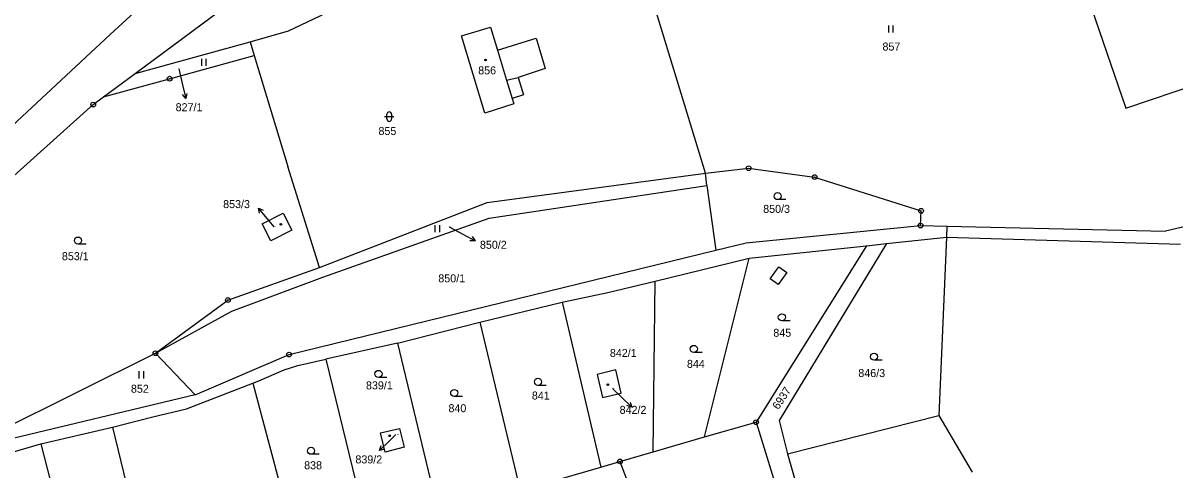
# Model space of a CAD drawing. Extents: x -593183 to -588034, y -1130415 to -1124994.
# Drawn here: x -592013.9 to -591769.2, y -1129007.5 to -1128912.6 of the extents above; entities that cross this region are included whole.
import ezdxf

# ---------------------------------------------------------------- set-up
doc = ezdxf.new("R2010")
doc.units = 0
for name, color, linetype in [('Vrstva 1', 7, 'Continuous'), ('Vrstva 16', 7, 'Continuous'), ('Vrstva 18', 7, 'Continuous'), ('Vrstva 19', 7, 'Continuous'), ('Vrstva 24', 7, 'Continuous'), ('Vrstva 25', 7, 'Continuous'), ('Vrstva 4', 7, 'Continuous')]:
    doc.layers.add(name, color=color, linetype=linetype)

msp = doc.modelspace()

# ---------------------------------------------------------------- linework, layer by layer
at = {"layer": 'Vrstva 1'}
for p, q in [((-591798.16, -1128876.43), (-591779.63, -1128930.63)), ((-591868.9, -1128944.44), (-591882.81, -1128898.89)), ((-591957.53, -1128914.23), (-591926.72, -1128899.6)), ((-591990.07, -1128923.29), (-591972.01, -1128909.95)), ((-591920.76, -1128915.28), (-591914.6, -1128913.44)), ((-591914.6, -1128913.44), (-591913.11, -1128918.34)), ((-591965.66, -1128916.58), (-591957.53, -1128914.23)), ((-591915.78, -1128931.72), (-591920.76, -1128915.28)), ((-591913.11, -1128918.34), (-591904.88, -1128915.79)), ((-591904.88, -1128915.79), (-591902.94, -1128922.26)), ((-591990.07, -1128923.29), (-591965.66, -1128916.58)), ((-591965.66, -1128916.58), (-591964.79, -1128919.47)), ((-591982.75, -1128924.4), (-591964.79, -1128919.47)), ((-591964.79, -1128919.47), (-591957.62, -1128943.06)), ((-591779.63, -1128930.63), (-591749.15, -1128920.45)), ((-591996.78, -1128928.26), (-591990.07, -1128923.29)), ((-591902.94, -1128922.26), (-591908.71, -1128924.16)), ((-591996.78, -1128928.26), (-591982.75, -1128924.4)), ((-591908.71, -1128924.16), (-591907.55, -1128927.85)), ((-591998.99, -1128929.89), (-591996.78, -1128928.26)), ((-591907.55, -1128927.85), (-591909.99, -1128928.59)), ((-592021.3, -1128949.87), (-591998.99, -1128929.89)), ((-591909.65, -1128929.71), (-591915.78, -1128931.72)), ((-591909.99, -1128928.59), (-591909.65, -1128929.71)), ((-591950.91, -1128964.5), (-591957.62, -1128943.06)), ((-591912.67, -1128950.37), (-591868.9, -1128944.44)), ((-591868.9, -1128944.44), (-591859.74, -1128943.42)), ((-591868.6, -1128947.12), (-591868.9, -1128944.44)), ((-591859.74, -1128943.42), (-591845.72, -1128945.3)), ((-591845.72, -1128945.3), (-591823.08, -1128952.47)), ((-591914.85, -1128954), (-591868.6, -1128947.12)), ((-591868.6, -1128947.12), (-591866.69, -1128960.82)), ((-591915.3, -1128950.73), (-591912.67, -1128950.37)), ((-591950.91, -1128964.5), (-591915.3, -1128950.73)), ((-591823.22, -1128955.59), (-591823.08, -1128952.47)), ((-591963.1, -1128955.2), (-591958.61, -1128952.97)), ((-591961.27, -1128958.84), (-591963.1, -1128955.2)), ((-591958.61, -1128952.97), (-591956.79, -1128956.59)), ((-591950.17, -1128966.57), (-591914.85, -1128954)), ((-591764.54, -1128955.26), (-591771.18, -1128956.77)), ((-591956.79, -1128956.59), (-591961.27, -1128958.84)), ((-591860.27, -1128959.25), (-591823.22, -1128955.59)), ((-591823.22, -1128955.59), (-591817.63, -1128955.72)), ((-591817.63, -1128955.72), (-591817.73, -1128958.08)), ((-591817.63, -1128955.72), (-591771.18, -1128956.77)), ((-591866.69, -1128960.82), (-591860.27, -1128959.25)), ((-591859.65, -1128962.55), (-591834.68, -1128959.89)), ((-591834.68, -1128959.89), (-591858.16, -1128997.37)), ((-591830.47, -1128959.44), (-591853.26, -1128997.03)), ((-591834.68, -1128959.89), (-591830.47, -1128959.44)), ((-591830.47, -1128959.44), (-591817.73, -1128958.08)), ((-591817.73, -1128958.08), (-591819.31, -1128995.97)), ((-591817.73, -1128958.08), (-591768.01, -1128959.56)), ((-591957.38, -1128982.99), (-591866.69, -1128960.82)), ((-591879.62, -1128967.39), (-591859.65, -1128962.55)), ((-591869.09, -1129000.5), (-591859.65, -1128962.55)), ((-591970.38, -1128971.43), (-591950.91, -1128964.5)), ((-591969.54, -1128973.78), (-591950.17, -1128966.57)), ((-591889.63, -1128969.81), (-591879.62, -1128967.39)), ((-591880.05, -1129003.67), (-591879.62, -1128967.39)), ((-591899.38, -1128971.86), (-591889.63, -1128969.81)), ((-591985.78, -1128982.71), (-591970.38, -1128971.43)), ((-591916.85, -1128976.13), (-591899.38, -1128971.86)), ((-591899.38, -1128971.86), (-591891.13, -1129006.89)), ((-591985.78, -1128982.71), (-591969.54, -1128973.78)), ((-591934.35, -1128980.55), (-591916.85, -1128976.13)), ((-591916.85, -1128976.13), (-591908.28, -1129011.87)), ((-591934.35, -1128980.55), (-591949.56, -1128983.97)), ((-591934.35, -1128980.55), (-591925.61, -1129016.89)), ((-592027.75, -1129003.63), (-591985.78, -1128982.71)), ((-591985.78, -1128982.71), (-591977.29, -1128991.55)), ((-591977.29, -1128991.55), (-591957.38, -1128982.99)), ((-591949.56, -1128983.97), (-591940.48, -1129021.2)), ((-591887.96, -1128986.26), (-591891.89, -1128987.2)), ((-591886.81, -1128991.2), (-591887.96, -1128986.26)), ((-591979.14, -1128994.54), (-591965.09, -1128989.08)), ((-591965.09, -1128989.08), (-591963.81, -1128988.59)), ((-591965.09, -1128989.08), (-591955.4, -1129025.36)), ((-591891.89, -1128987.2), (-591890.75, -1128992.11)), ((-591977.29, -1128991.55), (-592027.75, -1129003.63)), ((-591890.75, -1128992.11), (-591886.81, -1128991.2)), ((-591994.88, -1128998.43), (-591986.29, -1128996.22)), ((-591986.29, -1128996.22), (-591979.14, -1128994.54)), ((-591851.46, -1129004.08), (-591819.31, -1128995.97)), ((-591819.31, -1128995.97), (-591812.24, -1129007.95)), ((-592010.12, -1129001.94), (-591994.88, -1128998.43)), ((-591994.88, -1128998.43), (-591986.87, -1129031.29)), ((-591869.09, -1129000.5), (-591858.16, -1128997.37)), ((-591858.16, -1128997.37), (-591850.21, -1129022.94)), ((-591853.26, -1128997.03), (-591851.46, -1129004.08)), ((-591880.05, -1129003.67), (-591869.09, -1129000.5)), ((-592024.59, -1129006.21), (-592010.12, -1129001.94)), ((-592010.12, -1129001.94), (-592000.9, -1129037.72)), ((-591887.08, -1129005.69), (-591880.05, -1129003.67)), ((-591851.46, -1129004.08), (-591844.7, -1129027.89)), ((-591891.13, -1129006.89), (-591887.08, -1129005.69)), ((-591887.08, -1129005.69), (-591877.29, -1129031.67)), ((-591908.28, -1129011.87), (-591891.13, -1129006.89))]:
    msp.add_line(p, q, dxfattribs=at)
for points in [[(-591963.81, -1128988.59), (-591958.42, -1128986.25), (-591955.53, -1128985.34), (-591949.56, -1128983.97)], [(-591937.96, -1128999.66), (-591933.94, -1128998.68), (-591932.92, -1129002.7), (-591936.96, -1129003.7), (-591937.96, -1128999.66)]]:
    msp.add_lwpolyline(points, dxfattribs=at)
at = {"layer": 'Vrstva 16'}
for p, q in [((-591980.81, -1128922.31), (-591980.01, -1128925.7)), ((-591960.54, -1128955.89), (-591961.96, -1128954.19)), ((-591923.38, -1128955.89), (-591920.47, -1128957.43)), ((-591888.65, -1128990.2), (-591886.69, -1128992.1)), ((-591934.78, -1129000.05), (-591936.05, -1129001.3))]:
    msp.add_line(p, q, dxfattribs=at)
at = {"layer": 'Vrstva 24'}
for centre, radius in [((-591982.75, -1128924.4), 0.5), ((-591982.75, -1128924.4), 0.0327), ((-591998.99, -1128929.89), 0.5), ((-591998.99, -1128929.89), 0.0327), ((-591859.74, -1128943.42), 0.5), ((-591859.74, -1128943.42), 0.0327), ((-591845.72, -1128945.3), 0.5), ((-591845.72, -1128945.3), 0.0327), ((-591823.08, -1128952.47), 0.5), ((-591823.08, -1128952.47), 0.0327), ((-591823.22, -1128955.59), 0.5), ((-591823.22, -1128955.59), 0.0327), ((-591970.38, -1128971.43), 0.5), ((-591970.38, -1128971.43), 0.0327), ((-591985.78, -1128982.71), 0.5), ((-591985.78, -1128982.71), 0.0327), ((-591957.38, -1128982.99), 0.5), ((-591957.38, -1128982.99), 0.0327), ((-591858.16, -1128997.37), 0.5), ((-591858.16, -1128997.37), 0.0327), ((-591887.08, -1129005.69), 0.5), ((-591887.08, -1129005.69), 0.0327)]:
    msp.add_circle(centre, radius, dxfattribs=at)
at = {"layer": 'Vrstva 25'}
for p, q in [((-591830.04, -1128913.11), (-591830.04, -1128914.61)), ((-591829.02, -1128914.61), (-591829.02, -1128913.11)), ((-591975.98, -1128920.2), (-591975.98, -1128921.7)), ((-591974.96, -1128921.7), (-591974.96, -1128920.2)), ((-591980.01, -1128925.7), (-591979.32, -1128928.62)), ((-591937.09, -1128932.46), (-591935.09, -1128932.46)), ((-591936.59, -1128932.96), (-591936.59, -1128931.96)), ((-591935.59, -1128931.96), (-591935.59, -1128932.96)), ((-591851.81, -1128950.09), (-591853.56, -1128950.09)), ((-591961.96, -1128954.19), (-591963.88, -1128951.89)), ((-591926.38, -1128955.5), (-591926.38, -1128957)), ((-591925.35, -1128957), (-591925.35, -1128955.5)), ((-591920.47, -1128957.43), (-591917.82, -1128958.83)), ((-592000.47, -1128959.53), (-592002.22, -1128959.53)), ((-591850.93, -1128975.83), (-591852.68, -1128975.83)), ((-591869.63, -1128982.55), (-591871.38, -1128982.55)), ((-591831.34, -1128984.2), (-591833.09, -1128984.2)), ((-591989.26, -1128986.55), (-591989.26, -1128988.05)), ((-591988.23, -1128988.05), (-591988.23, -1128986.55)), ((-591936.63, -1128987.85), (-591938.38, -1128987.85)), ((-591902.74, -1128989.54), (-591904.49, -1128989.54)), ((-591920.54, -1128991.9), (-591922.29, -1128991.9)), ((-591886.69, -1128992.1), (-591884.53, -1128994.19)), ((-591936.05, -1129001.3), (-591938.19, -1129003.41)), ((-591950.95, -1129004.19), (-591952.7, -1129004.19))]:
    msp.add_line(p, q, dxfattribs=at)
for points in [[(-591979.06, -1128927.53), (-591979.32, -1128928.62), (-591980.04, -1128927.76)], [(-591963.63, -1128952.98), (-591963.88, -1128951.89), (-591962.86, -1128952.33)], [(-591918.47, -1128957.92), (-591917.82, -1128958.83), (-591918.94, -1128958.81)], [(-591884.91, -1128993.13), (-591884.53, -1128994.19), (-591885.6, -1128993.85)], [(-591937.12, -1129003.06), (-591938.19, -1129003.41), (-591937.83, -1129002.35)]]:
    msp.add_lwpolyline(points, dxfattribs=at)
for centre, radius in [((-591915.63, -1128920.43), 0.175), ((-591915.63, -1128920.43), 0.15), ((-591853.56, -1128949.34), 0.75), ((-591959.12, -1128955.35), 0.175), ((-591959.12, -1128955.35), 0.15), ((-592002.22, -1128958.78), 0.75), ((-591852.68, -1128975.08), 0.75), ((-591871.38, -1128981.8), 0.75), ((-591833.09, -1128983.45), 0.75), ((-591938.38, -1128987.1), 0.75), ((-591904.49, -1128988.79), 0.75), ((-591889.65, -1128989.41), 0.175), ((-591889.65, -1128989.41), 0.15), ((-591922.29, -1128991.15), 0.75), ((-591936, -1129000.26), 0.175), ((-591936, -1129000.26), 0.15), ((-591952.7, -1129003.44), 0.75)]:
    msp.add_circle(centre, radius, dxfattribs=at)
for centre, start, end in [((-591936.09, -1128931.96), 90, 180), ((-591936.09, -1128932.96), 180, 270), ((-591936.09, -1128931.96), 0, 90), ((-591936.09, -1128932.96), 270, 0)]:
    msp.add_arc(centre, 0.5, start, end, dxfattribs=at)
at = {"layer": 'Vrstva 4'}
for p, q in [((-591995.39, -1128915), (-591981.63, -1128902.32)), ((-592019.47, -1128937.42), (-591995.39, -1128915)), ((-591913.11, -1128918.34), (-591911.16, -1128924.75)), ((-591911.16, -1128924.75), (-591908.71, -1128924.16)), ((-591911.16, -1128924.75), (-591909.99, -1128928.59)), ((-591855.14, -1128966.93), (-591853.31, -1128964.37)), ((-591853.31, -1128964.37), (-591851.64, -1128965.56)), ((-591853.46, -1128968.13), (-591855.14, -1128966.93)), ((-591851.64, -1128965.56), (-591853.46, -1128968.13))]:
    msp.add_line(p, q, dxfattribs=at)

# ---------------------------------------------------------------- texts
at = {"layer": 'Vrstva 16'}
for s, p in [('827/1', (-591981.47, -1128931.31)), ('853/3', (-591971.38, -1128951.89)), ('850/2', (-591916.82, -1128960.53)), ('842/2', (-591887.14, -1128995.59)), ('839/2', (-591943.28, -1129006.12))]:
    msp.add_text(s, height=1.7, dxfattribs=at).set_placement(p)
at = {"layer": 'Vrstva 18'}
for s, height, p in [('857', 1.7, (-591831.3, -1128918.43)), ('827/1', 0.1, (-591980.81, -1128922.31)), ('855', 1.7, (-591938.38, -1128936.37)), ('850/3', 1.7, (-591856.64, -1128952.91)), ('850/2', 0.1, (-591923.38, -1128955.89)), ('853/1', 1.7, (-592005.64, -1128962.95)), ('850/1', 1.7, (-591925.66, -1128967.66)), ('845', 1.7, (-591854.49, -1128979.22)), ('842/1', 1.7, (-591889.21, -1128983.51)), ('844', 1.7, (-591872.84, -1128985.83)), ('846/3', 1.7, (-591836.43, -1128987.78)), ('852', 1.7, (-591990.97, -1128991.11)), ('839/1', 1.7, (-591941.03, -1128990.39)), ('841', 1.7, (-591905.79, -1128992.55)), ('840', 1.7, (-591923.51, -1128995.24)), ('838', 1.7, (-591954.17, -1129007.36))]:
    msp.add_text(s, height=height, dxfattribs=at).set_placement(p)
msp.add_text('6937', height=1.7, rotation=56.7175, dxfattribs=at).set_placement((-591853.41, -1128994.83))
at = {"layer": 'Vrstva 19'}
for s, height, p in [('856', 1.7, (-591917.19, -1128923.49)), ('853/3', 0.1, (-591960.54, -1128955.89)), ('842/2', 0.2, (-591888.65, -1128990.2)), ('839/2', 0.2, (-591934.78, -1129000.05))]:
    msp.add_text(s, height=height, dxfattribs=at).set_placement(p)

doc.saveas('drawing.dxf')
